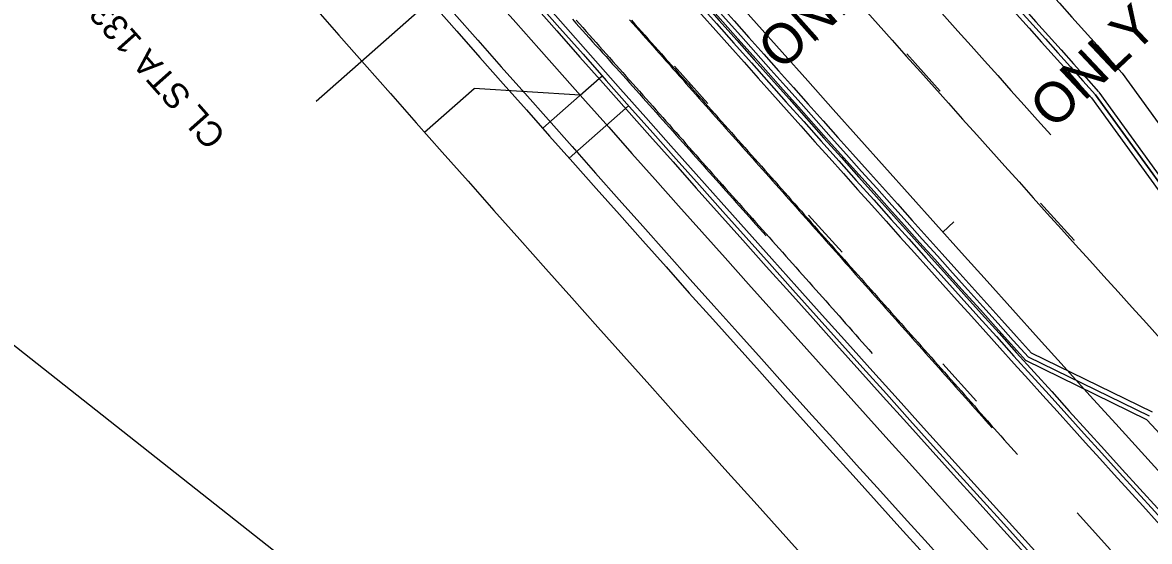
# Model space of a CAD drawing. Extents: x 2252205 to 2259955, y 13788514 to 13798103.
# Drawn here: x 2256409 to 2256634, y 13791951.4 to 13792055 of the extents above; entities that cross this region are included whole.
import ezdxf

# ---------------------------------------------------------------- set-up
doc = ezdxf.new("R2010")
doc.units = 0
for name, color, linetype in [('D_RDWY_TRACK_TRUCK_KLEIN_CITY', 7, 'Continuous'), ('D_TRAF_SIG_PR_CNDT', 7, 'Continuous'), ('GEOM_CENTERLINE_ALIGN', 7, 'Continuous'), ('GEOM_CENTERLINE_STA_100', 7, 'Continuous'), ('GEOM_CENTERLINE_STA_50', 7, 'Continuous'), ('ROAD_BIKE_SHARED_USE', 7, 'Continuous'), ('Road_Curb_Back', 7, 'Continuous'), ('Road_Curb_Face', 7, 'Continuous'), ('ROAD_DRIVEWAY_EP', 7, 'Continuous'), ('Road_EdgeOfPavementInside', 7, 'Continuous'), ('Road_EdgeOfPavementOutside', 7, 'Continuous'), ('ROAD_ROW_EXIST', 7, 'Continuous'), ('ROAD_ROW_PROPOSED', 7, 'Continuous'), ('ROAD_SCRATCH_DRIVE_CL', 7, 'Continuous'), ('ROAD_SCRATCH_EP_CONTROL', 7, 'Continuous'), ('Road_Sidewalk_Back', 7, 'Continuous'), ('TRAF_PAVMRK_W_4IN_BRK', 7, 'Continuous'), ('TRAF_PAVMRK_W_4IN_SLD', 7, 'Continuous'), ('TRAF_PAVMRK_W_8IN_SLD', 7, 'Continuous'), ('TRAF_PAVMRK_W_LT_TRN_ARROW_WORD', 7, 'Continuous'), ('TRAF_PAVMRK_W_RT_TRN_ARROW_WORD', 7, 'Continuous'), ('TRAF_PAVMRK_Y_4IN_SLD', 7, 'Continuous')]:
    doc.layers.add(name, color=color, linetype=linetype)

msp = doc.modelspace()

# ---------------------------------------------------------------- linework, layer by layer
at = {"layer": 'D_RDWY_TRACK_TRUCK_KLEIN_CITY'}
for points in [[(2256518.81, 13792055.66), (2256519.48, 13792054.92), (2256520.14, 13792054.17), (2256520.81, 13792053.43), (2256521.48, 13792052.68), (2256522.15, 13792051.94), (2256522.81, 13792051.19), (2256523.48, 13792050.45), (2256524.15, 13792049.7), (2256524.81, 13792048.96), (2256525.48, 13792048.22), (2256526.15, 13792047.47), (2256526.81, 13792046.73), (2256527.48, 13792045.98), (2256528.15, 13792045.24), (2256528.81, 13792044.49), (2256529.48, 13792043.75), (2256530.15, 13792043), (2256530.81, 13792042.26), (2256531.48, 13792041.51), (2256532.15, 13792040.77), (2256532.81, 13792040.02), (2256533.48, 13792039.27), (2256534.14, 13792038.53), (2256534.81, 13792037.78), (2256535.48, 13792037.04), (2256536.14, 13792036.29), (2256536.81, 13792035.55), (2256537.47, 13792034.8), (2256538.14, 13792034.06), (2256538.81, 13792033.31), (2256539.47, 13792032.56), (2256540.14, 13792031.82), (2256540.8, 13792031.07), (2256541.47, 13792030.33), (2256542.14, 13792029.58), (2256542.8, 13792028.84), (2256543.47, 13792028.09), (2256544.13, 13792027.34), (2256544.8, 13792026.6), (2256545.46, 13792025.85), (2256546.13, 13792025.1), (2256546.79, 13792024.36), (2256547.46, 13792023.61), (2256548.13, 13792022.87), (2256548.79, 13792022.12), (2256549.46, 13792021.37), (2256550.12, 13792020.63), (2256550.79, 13792019.88), (2256551.45, 13792019.13), (2256552.12, 13792018.39), (2256552.78, 13792017.64), (2256553.45, 13792016.9), (2256554.11, 13792016.15), (2256554.78, 13792015.4), (2256555.44, 13792014.66), (2256556.11, 13792013.91), (2256556.77, 13792013.16), (2256557.44, 13792012.42)], [(2256519.52, 13792055.49), (2256520.19, 13792054.75), (2256520.85, 13792054), (2256521.52, 13792053.25), (2256522.18, 13792052.5), (2256522.85, 13792051.76), (2256523.51, 13792051.01), (2256524.18, 13792050.26), (2256524.84, 13792049.51), (2256525.5, 13792048.77), (2256526.17, 13792048.02), (2256526.83, 13792047.27), (2256527.5, 13792046.53), (2256528.16, 13792045.78), (2256528.83, 13792045.03), (2256529.49, 13792044.28), (2256530.16, 13792043.54), (2256530.82, 13792042.79), (2256531.48, 13792042.04), (2256532.15, 13792041.29), (2256532.81, 13792040.55), (2256533.48, 13792039.8), (2256534.14, 13792039.05), (2256534.81, 13792038.3), (2256535.47, 13792037.56), (2256536.14, 13792036.81), (2256536.8, 13792036.06), (2256537.46, 13792035.31), (2256538.13, 13792034.57), (2256538.79, 13792033.82), (2256539.46, 13792033.07), (2256540.12, 13792032.33), (2256540.79, 13792031.58), (2256541.45, 13792030.83), (2256542.11, 13792030.08), (2256542.78, 13792029.34), (2256543.44, 13792028.59), (2256544.11, 13792027.84), (2256544.77, 13792027.09), (2256545.44, 13792026.35), (2256546.1, 13792025.6), (2256546.77, 13792024.85), (2256547.43, 13792024.1), (2256548.09, 13792023.36), (2256548.76, 13792022.61), (2256549.42, 13792021.86), (2256550.09, 13792021.11), (2256550.75, 13792020.37), (2256551.42, 13792019.62), (2256552.08, 13792018.87), (2256552.75, 13792018.13), (2256553.41, 13792017.38), (2256554.07, 13792016.63), (2256554.74, 13792015.88), (2256555.4, 13792015.14), (2256556.07, 13792014.39), (2256556.73, 13792013.64), (2256557.4, 13792012.89), (2256558.06, 13792012.15), (2256558.73, 13792011.4), (2256559.39, 13792010.65), (2256560.05, 13792009.9), (2256560.72, 13792009.16), (2256561.38, 13792008.41), (2256562.05, 13792007.66), (2256562.71, 13792006.91), (2256563.38, 13792006.17), (2256564.04, 13792005.42), (2256564.7, 13792004.67), (2256565.37, 13792003.93), (2256566.03, 13792003.18), (2256566.7, 13792002.43), (2256567.36, 13792001.68), (2256568.03, 13792000.94), (2256568.69, 13792000.19), (2256569.36, 13791999.44), (2256570.02, 13791998.69), (2256570.68, 13791997.95), (2256571.35, 13791997.2), (2256572.01, 13791996.45), (2256572.68, 13791995.7), (2256573.34, 13791994.96), (2256574.01, 13791994.21), (2256574.67, 13791993.46), (2256575.34, 13791992.71), (2256576, 13791991.97), (2256576.66, 13791991.22), (2256577.33, 13791990.47), (2256577.99, 13791989.73), (2256578.66, 13791988.98)], [(2256530.16, 13792055.58), (2256530.82, 13792054.83), (2256531.48, 13792054.08), (2256532.15, 13792053.34), (2256532.81, 13792052.59), (2256533.48, 13792051.84), (2256534.14, 13792051.09), (2256534.81, 13792050.35), (2256535.47, 13792049.6), (2256536.13, 13792048.85), (2256536.8, 13792048.1), (2256537.46, 13792047.36), (2256538.13, 13792046.61), (2256538.79, 13792045.86), (2256539.46, 13792045.11), (2256540.12, 13792044.37), (2256540.79, 13792043.62), (2256541.45, 13792042.87), (2256542.11, 13792042.13), (2256542.78, 13792041.38), (2256543.44, 13792040.63), (2256544.11, 13792039.88), (2256544.77, 13792039.14), (2256545.44, 13792038.39), (2256546.1, 13792037.64), (2256546.77, 13792036.89), (2256547.43, 13792036.15), (2256548.09, 13792035.4), (2256548.76, 13792034.65), (2256549.42, 13792033.9), (2256550.09, 13792033.16), (2256550.75, 13792032.41), (2256551.42, 13792031.66), (2256552.08, 13792030.91), (2256552.74, 13792030.17), (2256553.41, 13792029.42), (2256554.07, 13792028.67), (2256554.74, 13792027.92), (2256555.4, 13792027.18), (2256556.07, 13792026.43), (2256556.73, 13792025.68), (2256557.4, 13792024.94), (2256558.06, 13792024.19), (2256558.72, 13792023.44), (2256559.39, 13792022.69), (2256560.05, 13792021.95), (2256560.72, 13792021.2), (2256561.38, 13792020.45), (2256562.05, 13792019.7), (2256562.71, 13792018.96), (2256563.38, 13792018.21), (2256564.04, 13792017.46), (2256564.7, 13792016.71), (2256565.37, 13792015.97), (2256566.03, 13792015.22), (2256566.7, 13792014.47), (2256567.36, 13792013.72), (2256568.03, 13792012.98), (2256568.69, 13792012.23), (2256569.36, 13792011.48), (2256570.02, 13792010.74), (2256570.68, 13792009.99), (2256571.35, 13792009.24), (2256572.01, 13792008.49), (2256572.68, 13792007.75), (2256573.34, 13792007), (2256574.01, 13792006.25), (2256574.67, 13792005.5), (2256575.33, 13792004.76), (2256576, 13792004.01), (2256576.66, 13792003.26), (2256577.33, 13792002.51), (2256577.99, 13792001.77), (2256578.66, 13792001.02), (2256579.32, 13792000.27), (2256579.99, 13791999.52), (2256580.65, 13791998.78), (2256581.31, 13791998.03), (2256581.98, 13791997.28), (2256582.64, 13791996.54), (2256583.31, 13791995.79), (2256583.97, 13791995.04), (2256584.64, 13791994.29), (2256585.3, 13791993.55), (2256585.97, 13791992.8), (2256586.63, 13791992.05), (2256587.29, 13791991.3), (2256587.96, 13791990.56), (2256588.62, 13791989.81), (2256589.29, 13791989.06), (2256589.95, 13791988.31), (2256590.62, 13791987.57), (2256591.28, 13791986.82), (2256591.94, 13791986.07), (2256592.61, 13791985.32), (2256593.27, 13791984.58), (2256593.94, 13791983.83), (2256594.6, 13791983.08), (2256595.27, 13791982.34), (2256595.93, 13791981.59), (2256596.6, 13791980.84), (2256597.26, 13791980.09), (2256597.92, 13791979.35), (2256598.59, 13791978.6), (2256599.25, 13791977.85), (2256599.92, 13791977.1), (2256600.58, 13791976.36), (2256601.25, 13791975.61), (2256601.91, 13791974.86), (2256602.58, 13791974.11)], [(2256530.6, 13792055.47), (2256531.27, 13792054.72), (2256531.93, 13792053.97), (2256532.6, 13792053.22), (2256533.26, 13792052.48), (2256533.92, 13792051.73), (2256534.59, 13792050.98), (2256535.25, 13792050.23), (2256535.92, 13792049.49), (2256536.58, 13792048.74), (2256537.25, 13792047.99), (2256537.91, 13792047.24), (2256538.57, 13792046.5), (2256539.24, 13792045.75), (2256539.9, 13792045), (2256540.57, 13792044.26), (2256541.23, 13792043.51), (2256541.9, 13792042.76), (2256542.56, 13792042.01), (2256543.23, 13792041.27), (2256543.89, 13792040.52), (2256544.55, 13792039.77), (2256545.22, 13792039.02), (2256545.88, 13792038.28), (2256546.55, 13792037.53), (2256547.21, 13792036.78), (2256547.88, 13792036.03), (2256548.54, 13792035.29), (2256549.21, 13792034.54), (2256549.87, 13792033.79), (2256550.53, 13792033.04), (2256551.2, 13792032.3), (2256551.86, 13792031.55), (2256552.53, 13792030.8), (2256553.19, 13792030.06), (2256553.86, 13792029.31), (2256554.52, 13792028.56), (2256555.18, 13792027.81), (2256555.85, 13792027.07), (2256556.51, 13792026.32), (2256557.18, 13792025.57), (2256557.84, 13792024.82), (2256558.51, 13792024.08), (2256559.17, 13792023.33), (2256559.84, 13792022.58), (2256560.5, 13792021.83), (2256561.16, 13792021.09), (2256561.83, 13792020.34), (2256562.49, 13792019.59), (2256563.16, 13792018.84), (2256563.82, 13792018.1), (2256564.49, 13792017.35), (2256565.15, 13792016.6), (2256565.82, 13792015.85), (2256566.48, 13792015.11), (2256567.14, 13792014.36), (2256567.81, 13792013.61), (2256568.47, 13792012.87), (2256569.14, 13792012.12), (2256569.8, 13792011.37), (2256570.47, 13792010.62), (2256571.13, 13792009.88), (2256571.8, 13792009.13), (2256572.46, 13792008.38), (2256573.12, 13792007.63), (2256573.79, 13792006.89), (2256574.45, 13792006.14), (2256575.12, 13792005.39), (2256575.78, 13792004.64), (2256576.45, 13792003.9), (2256577.11, 13792003.15), (2256577.77, 13792002.4), (2256578.44, 13792001.65), (2256579.1, 13792000.91), (2256579.77, 13792000.16), (2256580.43, 13791999.41), (2256581.1, 13791998.67), (2256581.76, 13791997.92), (2256582.43, 13791997.17), (2256583.09, 13791996.42), (2256583.75, 13791995.68), (2256584.42, 13791994.93), (2256585.08, 13791994.18), (2256585.75, 13791993.43), (2256586.41, 13791992.69), (2256587.08, 13791991.94), (2256587.74, 13791991.19), (2256588.41, 13791990.44), (2256589.07, 13791989.7), (2256589.73, 13791988.95), (2256590.4, 13791988.2), (2256591.06, 13791987.45), (2256591.73, 13791986.71), (2256592.39, 13791985.96), (2256593.06, 13791985.21), (2256593.72, 13791984.47), (2256594.39, 13791983.72), (2256595.05, 13791982.97), (2256595.71, 13791982.22), (2256596.38, 13791981.48), (2256597.04, 13791980.73), (2256597.71, 13791979.98), (2256598.37, 13791979.23), (2256599.04, 13791978.49), (2256599.7, 13791977.74), (2256600.36, 13791976.99), (2256601.03, 13791976.24), (2256601.69, 13791975.5), (2256602.36, 13791974.75), (2256603.02, 13791974), (2256603.69, 13791973.25), (2256604.35, 13791972.51), (2256605.02, 13791971.76), (2256605.68, 13791971.01), (2256606.34, 13791970.27), (2256607.01, 13791969.52), (2256607.67, 13791968.77)]]:
    msp.add_lwpolyline(points, dxfattribs=at)
at = {"layer": 'D_TRAF_SIG_PR_CNDT'}
msp.add_line((2256575.17, 13791858.1), (2256397.42, 13791998.27), dxfattribs=at)
at = {"layer": 'GEOM_CENTERLINE_ALIGN'}
msp.add_arc((2265119, 13799669.27), 11459.16, 219.418553, 224.327385, dxfattribs=at)
at = {"layer": 'GEOM_CENTERLINE_STA_100'}
msp.add_line((2256592.74, 13792013.21), (2256594.97, 13792015.22), dxfattribs=at)
at = {"layer": 'GEOM_CENTERLINE_STA_50'}
msp.add_line((2256592.74, 13792013.21), (2256593.85, 13792014.22), dxfattribs=at)
at = {"layer": 'ROAD_BIKE_SHARED_USE'}
for p, q in [((2256512.85, 13792033.92), (2256524.71, 13792044.38)), ((2256518.14, 13792027.92), (2256530, 13792038.38))]:
    msp.add_line(p, q, dxfattribs=at)
for radius, start, end in [(11494.99, 220.925074, 223.155573), (11504.99, 220.928174, 223.15647)]:
    msp.add_arc((2265119, 13799669.27), radius, start, end, dxfattribs=at)
at = {"layer": 'Road_Curb_Back'}
for p, q in [((2256623.89, 13792041.13), (2256682.66, 13791959.87)), ((2256633.5, 13791975.75), (2256609.34, 13791987.54))]:
    msp.add_line(p, q, dxfattribs=at)
for radius, start, end in [(11417.33, 220.716833, 221.921868), (11464.33, 220.621764, 222.296129), (11463.99, 220.621764, 222.072794), (11489.99, 220.923263, 223.155124), (11453.99, 222.197552, 223.071947)]:
    msp.add_arc((2265119, 13799669.27), radius, start, end, dxfattribs=at)
at = {"layer": 'Road_Curb_Face'}
msp.add_line((2256623.24, 13792040.61), (2256682.02, 13791959.34), dxfattribs=at)
for radius, start, end in [(11418.16, 220.716833, 221.921868), (11489.16, 220.923263, 223.155049)]:
    msp.add_arc((2265119, 13799669.27), radius, start, end, dxfattribs=at)
at = {"layer": 'ROAD_DRIVEWAY_EP'}
for p, q in [((2256520.33, 13792040.52), (2256524.71, 13792044.38)), ((2256489.26, 13792033.12), (2256499.13, 13792041.83)), ((2256520.33, 13792040.52), (2256499.13, 13792041.83))]:
    msp.add_line(p, q, dxfattribs=at)
at = {"layer": 'Road_EdgeOfPavementInside'}
msp.add_line((2256634.01, 13791976.43), (2256609.85, 13791988.22), dxfattribs=at)
for radius, end in [(11463.16, 222.071988), (11465.16, 222.296933)]:
    msp.add_arc((2265119, 13799669.27), radius, 220.621764, end, dxfattribs=at)
at = {"layer": 'Road_EdgeOfPavementOutside'}
msp.add_line((2256682.02, 13791959.34), (2256623.24, 13792040.61), dxfattribs=at)
for radius, start, end in [(11418.16, 220.716833, 221.921868), (11489.16, 220.923263, 223.155049)]:
    msp.add_arc((2265119, 13799669.27), radius, start, end, dxfattribs=at)
at = {"layer": 'ROAD_ROW_EXIST'}
msp.add_arc((2265124.02, 13799672.91), 11509.2, 220.760702, 223.023397, dxfattribs=at)
at = {"layer": 'ROAD_ROW_PROPOSED'}
msp.add_arc((2265116.03, 13799666.59), 11519.16, 220.67779, 223.158467, dxfattribs=at)
at = {"layer": 'ROAD_SCRATCH_DRIVE_CL'}
msp.add_line((2256467.57, 13792039.33), (2256524.68, 13792089.69), dxfattribs=at)
at = {"layer": 'Road_Sidewalk_Back'}
msp.add_line((2256628.57, 13792044.9), (2256687.32, 13791963.66), dxfattribs=at)
msp.add_arc((2265119, 13799669.27), 11411.33, 220.716833, 221.92368, dxfattribs=at)
at = {"layer": 'TRAF_PAVMRK_W_4IN_BRK'}
for points in [[(2256592.23, 13792041.32), (2256585.54, 13792048.76)], [(2256539.14, 13792046.3), (2256539.14, 13792046.29)], [(2256539.14, 13792046.29), (2256545.84, 13792038.87)], [(2256592.23, 13792041.31), (2256592.23, 13792041.32)], [(2256618.96, 13792011.55), (2256612.28, 13792018.99)], [(2256565.94, 13792016.6), (2256565.94, 13792016.59)], [(2256565.94, 13792016.59), (2256572.64, 13792009.16)], [(2256618.97, 13792011.54), (2256618.96, 13792011.55)], [(2256592.74, 13791986.89), (2256592.75, 13791986.88)], [(2256592.75, 13791986.88), (2256599.44, 13791979.46)], [(2256619.54, 13791957.18), (2256619.55, 13791957.17)], [(2256619.55, 13791957.17), (2256626.25, 13791949.75)]]:
    msp.add_lwpolyline(points, dxfattribs=at)
msp.add_arc((2265119, 13799669.27), 11441.16, 220.646831, 223.351209, dxfattribs=at)
at = {"layer": 'TRAF_PAVMRK_W_4IN_SLD'}
msp.add_line((2256622.46, 13792039.98), (2256681.24, 13791958.71), dxfattribs=at)
for radius, start, end in [(11419.16, 220.716833, 221.921868), (11488.16, 220.923263, 223.335434)]:
    msp.add_arc((2265119, 13799669.27), radius, start, end, dxfattribs=at)
at = {"layer": 'TRAF_PAVMRK_W_8IN_SLD'}
for radius, start, end in [(11430.16, 220.64686, 221.921868), (11452.16, 220.646802, 221.696394)]:
    msp.add_arc((2265119, 13799669.27), radius, start, end, dxfattribs=at)
at = {"layer": 'TRAF_PAVMRK_Y_4IN_SLD'}
msp.add_line((2256634.62, 13791977.24), (2256610.47, 13791989.03), dxfattribs=at)
for radius, start, end in [(11466.16, 220.621747, 223.342802), (11462.16, 220.646776, 222.071021)]:
    msp.add_arc((2265119, 13799669.27), radius, start, end, dxfattribs=at)

# ---------------------------------------------------------------- texts
at = {"layer": 'ROAD_SCRATCH_EP_CONTROL'}
msp.add_text('CL STA 1338+99.72', height=5, rotation=131.5783, dxfattribs=at).set_placement((2256449.83, 13792032.58))
at = {"layer": 'TRAF_PAVMRK_W_LT_TRN_ARROW_WORD'}
msp.add_text('ONLY', height=8, rotation=41.7015, dxfattribs=at).set_placement((2256560.36, 13792045.16))
at = {"layer": 'TRAF_PAVMRK_W_RT_TRN_ARROW_WORD'}
msp.add_text('ONLY', height=8, rotation=43.3314, dxfattribs=at).set_placement((2256614.84, 13792033.45))

doc.saveas('drawing.dxf')
